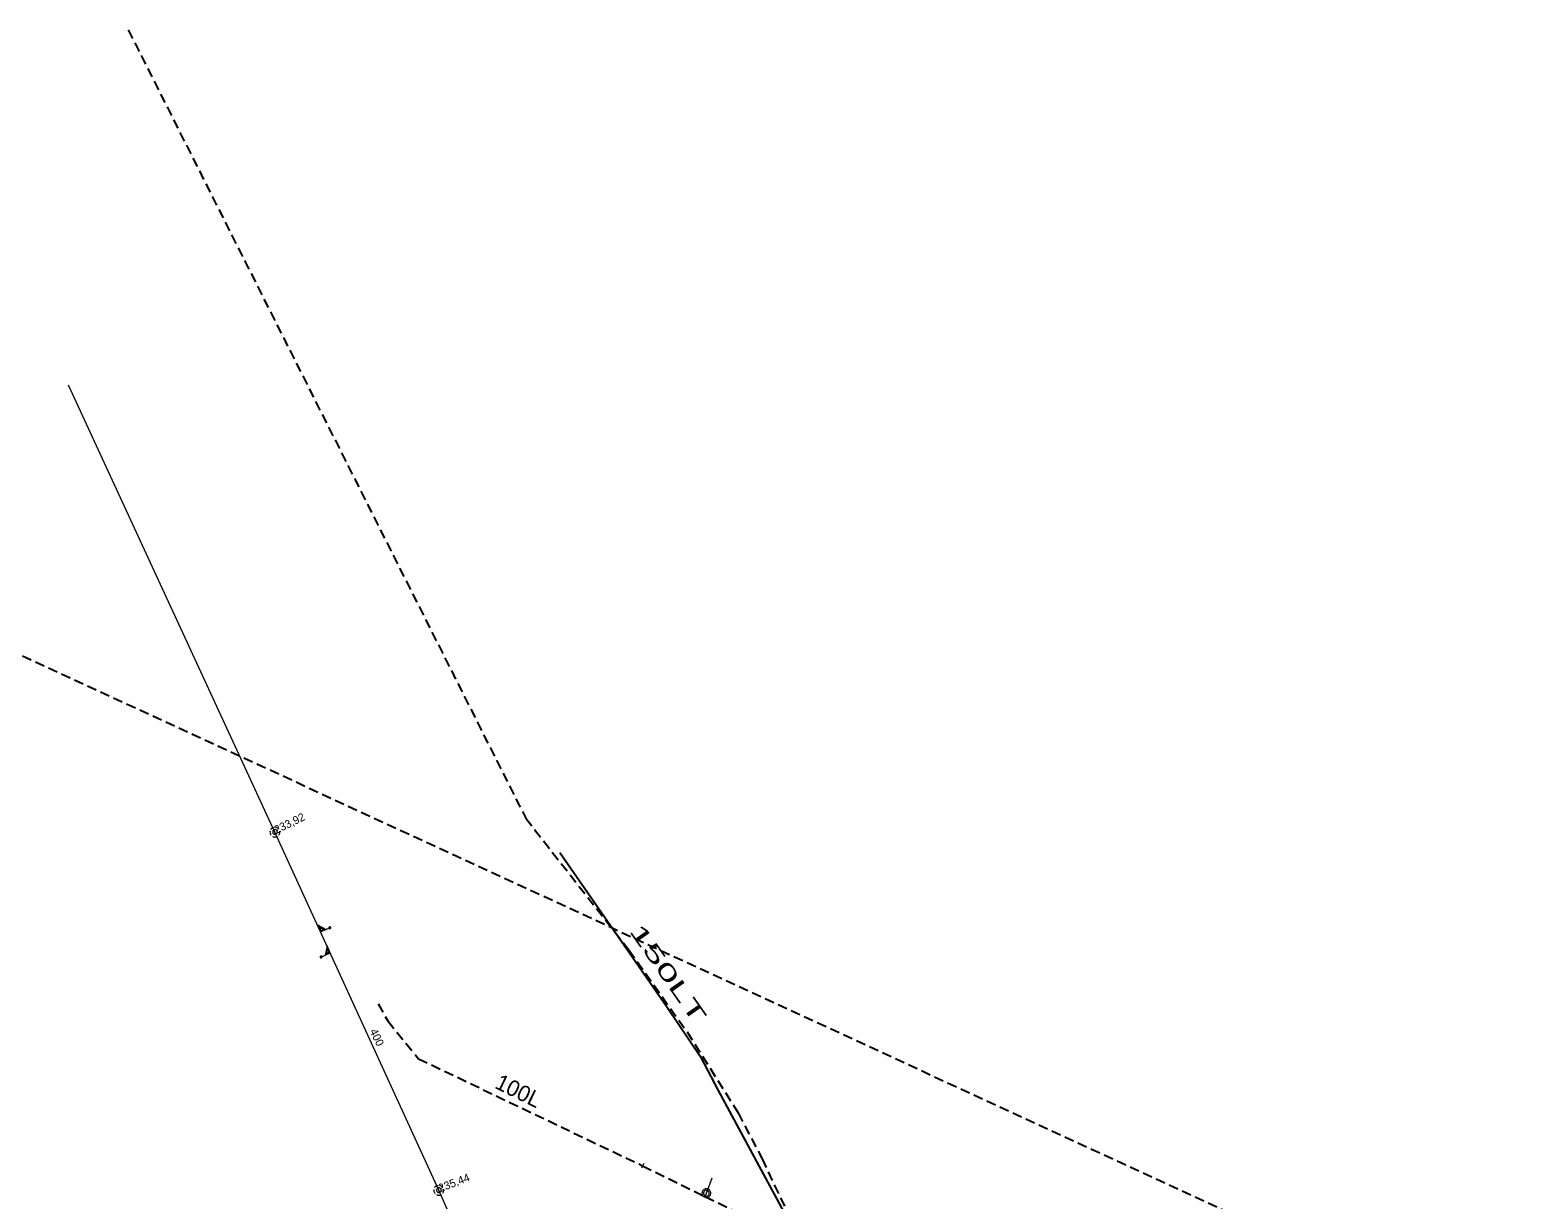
# Model space of a CAD drawing. Extents: x -735085 to -733500, y -1044153 to -1043402.
# Drawn here: x -734892.7 to -734742.3, y -1043519.6 to -1043402.3 of the extents above; entities that cross this region are included whole.
import ezdxf

# ---------------------------------------------------------------- set-up
doc = ezdxf.new("R2010")
doc.units = 0
doc.header["$LTSCALE"] = 0.32
doc.linetypes.add('MEDIUM_DASHED', pattern=[4.5, 3, -1.5])
doc.layers.add('15', color=7, linetype='Continuous')
doc.layers.add('16', color=7, linetype='Continuous')
for name, color, linetype, lineweight in [('18', 7, 'Continuous', 13), ('20', 7, 'Continuous', 13), ('63', 7, 'MEDIUM_DASHED', 25), ('8', 7, 'Continuous', 13)]:
    doc.layers.add(name, color=color, linetype=linetype, lineweight=lineweight)

msp = doc.modelspace()

# ---------------------------------------------------------------- linework, layer by layer
at = {"layer": '18'}
for points in [[(-734868.658, -1043482.699), (-734868.664, -1043482.776), (-734868.659, -1043482.853), (-734868.642, -1043482.928), (-734868.613, -1043482.999), (-734868.573, -1043483.065), (-734868.557, -1043483.087)], [(-734868.313, -1043482.307), (-734868.384, -1043482.335), (-734868.451, -1043482.374), (-734868.511, -1043482.422), (-734868.562, -1043482.479), (-734868.586, -1043482.513)], [(-734867.772, -1043482.49), (-734867.822, -1043482.432), (-734867.88, -1043482.382), (-734867.945, -1043482.341), (-734868.016, -1043482.312), (-734868.065, -1043482.298)], [(-734867.777, -1043483.076), (-734867.736, -1043483.011), (-734867.705, -1043482.941), (-734867.686, -1043482.866), (-734867.678, -1043482.79), (-734867.683, -1043482.713), (-734867.689, -1043482.678)], [(-734868.4, -1043483.216), (-734868.33, -1043483.247), (-734868.255, -1043483.266), (-734868.179, -1043483.273), (-734868.102, -1043483.268), (-734868.027, -1043483.251), (-734867.955, -1043483.223), (-734867.895, -1043483.188)], [(-734862.571, -1043492.344), (-734863.567, -1043492.8), (-734863.887, -1043492.099), (-734863.041, -1043492.559)], [(-734863.169, -1043492.563), (-734863.548, -1043492.736), (-734863.783, -1043492.221), (-734863.169, -1043492.562)], [(-734863.265, -1043492.555), (-734863.531, -1043492.676), (-734863.686, -1043492.338), (-734863.265, -1043492.556)], [(-734863.613, -1043495.348), (-734862.617, -1043494.892), (-734862.938, -1043494.191), (-734863.143, -1043495.133)], [(-734863.056, -1043495.037), (-734862.678, -1043494.864), (-734862.913, -1043494.349), (-734863.058, -1043495.038)], [(-734863, -1043494.959), (-734862.734, -1043494.838), (-734862.889, -1043494.501), (-734863, -1043494.96)], [(-734852.217, -1043518.649), (-734852.223, -1043518.726), (-734852.218, -1043518.803), (-734852.201, -1043518.878), (-734852.172, -1043518.949), (-734852.132, -1043519.015), (-734852.116, -1043519.037)], [(-734851.872, -1043518.257), (-734851.943, -1043518.285), (-734852.01, -1043518.324), (-734852.07, -1043518.372), (-734852.121, -1043518.429), (-734852.145, -1043518.463)], [(-734851.959, -1043519.166), (-734851.889, -1043519.197), (-734851.814, -1043519.216), (-734851.738, -1043519.223), (-734851.661, -1043519.218), (-734851.586, -1043519.201), (-734851.514, -1043519.173), (-734851.454, -1043519.138)], [(-734851.331, -1043518.44), (-734851.381, -1043518.382), (-734851.439, -1043518.332), (-734851.504, -1043518.291), (-734851.575, -1043518.262), (-734851.624, -1043518.248)], [(-734851.336, -1043519.026), (-734851.295, -1043518.961), (-734851.264, -1043518.891), (-734851.245, -1043518.816), (-734851.237, -1043518.74), (-734851.242, -1043518.663), (-734851.248, -1043518.628)]]:
    msp.add_lwpolyline(points, dxfattribs=at)
for points in [[(-734867.929, -1043482.759), (-734867.935, -1043482.707), (-734867.953, -1043482.657), (-734867.981, -1043482.613), (-734868.019, -1043482.576), (-734868.064, -1043482.549), (-734868.114, -1043482.533), (-734868.166, -1043482.528), (-734868.218, -1043482.535), (-734868.267, -1043482.554), (-734868.311, -1043482.584), (-734868.346, -1043482.623), (-734868.372, -1043482.668), (-734868.387, -1043482.719), (-734868.39, -1043482.771), (-734868.382, -1043482.823), (-734868.361, -1043482.871), (-734868.331, -1043482.914), (-734868.291, -1043482.949), (-734868.245, -1043482.973), (-734868.194, -1043482.987), (-734868.142, -1043482.989), (-734868.09, -1043482.979), (-734868.042, -1043482.957), (-734868, -1043482.925), (-734867.967, -1043482.885), (-734867.943, -1043482.838), (-734867.931, -1043482.787)], [(-734862.696, -1043492.298), (-734862.723, -1043492.317), (-734862.743, -1043492.344), (-734862.751, -1043492.377), (-734862.747, -1043492.41), (-734862.732, -1043492.44), (-734862.707, -1043492.462), (-734862.676, -1043492.476), (-734862.642, -1043492.477), (-734862.611, -1043492.466), (-734862.585, -1043492.445), (-734862.568, -1043492.416), (-734862.562, -1043492.383), (-734862.568, -1043492.351), (-734862.585, -1043492.321), (-734862.611, -1043492.3), (-734862.643, -1043492.29), (-734862.677, -1043492.291)], [(-734862.685, -1043492.323), (-734862.708, -1043492.34), (-734862.723, -1043492.364), (-734862.724, -1043492.392), (-734862.715, -1043492.419), (-734862.696, -1043492.44), (-734862.669, -1043492.449), (-734862.641, -1043492.449), (-734862.616, -1043492.436), (-734862.598, -1043492.415), (-734862.591, -1043492.387), (-734862.595, -1043492.359), (-734862.61, -1043492.336), (-734862.635, -1043492.32), (-734862.662, -1043492.316)], [(-734863.567, -1043495.222), (-734863.595, -1043495.241), (-734863.614, -1043495.269), (-734863.622, -1043495.301), (-734863.618, -1043495.334), (-734863.603, -1043495.364), (-734863.579, -1043495.387), (-734863.547, -1043495.4), (-734863.514, -1043495.401), (-734863.482, -1043495.391), (-734863.456, -1043495.369), (-734863.439, -1043495.341), (-734863.433, -1043495.308), (-734863.44, -1043495.275), (-734863.456, -1043495.246), (-734863.482, -1043495.225), (-734863.514, -1043495.215), (-734863.548, -1043495.216)], [(-734863.554, -1043495.246), (-734863.577, -1043495.263), (-734863.591, -1043495.288), (-734863.594, -1043495.316), (-734863.583, -1043495.343), (-734863.564, -1043495.363), (-734863.538, -1043495.374), (-734863.51, -1043495.373), (-734863.484, -1043495.36), (-734863.467, -1043495.338), (-734863.459, -1043495.311), (-734863.464, -1043495.283), (-734863.478, -1043495.26), (-734863.503, -1043495.244), (-734863.531, -1043495.24)], [(-734851.488, -1043518.709), (-734851.494, -1043518.657), (-734851.512, -1043518.607), (-734851.54, -1043518.563), (-734851.578, -1043518.526), (-734851.623, -1043518.499), (-734851.673, -1043518.483), (-734851.725, -1043518.478), (-734851.777, -1043518.485), (-734851.826, -1043518.504), (-734851.87, -1043518.534), (-734851.905, -1043518.573), (-734851.931, -1043518.618), (-734851.946, -1043518.669), (-734851.949, -1043518.721), (-734851.941, -1043518.773), (-734851.92, -1043518.821), (-734851.89, -1043518.864), (-734851.85, -1043518.899), (-734851.804, -1043518.923), (-734851.753, -1043518.937), (-734851.701, -1043518.939), (-734851.649, -1043518.929), (-734851.601, -1043518.907), (-734851.559, -1043518.875), (-734851.526, -1043518.835), (-734851.502, -1043518.788), (-734851.49, -1043518.737)]]:
    msp.add_lwpolyline(points, close=True, dxfattribs=at)
at = {"layer": '20'}
msp.add_line((-734827.03, -1043574.42), (-734851.719, -1043518.72), dxfattribs=at)
msp.add_line((-734827.03, -1043574.42), (-734851.719, -1043518.72), dxfattribs=at)
msp.add_lwpolyline([(-734851.719, -1043518.72), (-734868.16, -1043482.77), (-734888.879, -1043437.93)], dxfattribs=at)
msp.add_lwpolyline([(-734851.719, -1043518.72), (-734868.16, -1043482.77), (-734888.879, -1043437.93)], dxfattribs=at)
at = {"layer": '63'}
msp.add_lwpolyline([(-734796.022, -1043808.279), (-734957.658, -1043641.023), (-734957.66, -1043641.021), (-735032.487, -1043496.398), (-735032.488, -1043496.396), (-735032.488, -1043496.394), (-735032.488, -1043496.393), (-735032.488, -1043496.391), (-735014.686, -1043433.916), (-735014.686, -1043433.914), (-735014.685, -1043433.913), (-735014.683, -1043433.911), (-735014.682, -1043433.91), (-735014.68, -1043433.909), (-735014.678, -1043433.909), (-735014.676, -1043433.909), (-734957.569, -1043435.5), (-734957.567, -1043435.5), (-734957.565, -1043435.501), (-734250.468, -1043761.931)], dxfattribs=at)
at = {"layer": '8'}
msp.add_line((-734831.162, -1043516.042), (-734831.385, -1043516.509), dxfattribs=at)
at = {"layer": '8', "linetype": 'MEDIUM_DASHED', "lineweight": 25}
for points in [[(-734882.879, -1043402.28), (-734843, -1043481.39), (-734832.66, -1043494.6), (-734826.809, -1043502.83), (-734821.69, -1043510.97), (-734819.3, -1043515.56), (-734816.109, -1043522.33)], [(-734857.796, -1043500.009), (-734856.844, -1043501.735), (-734853.754, -1043505.523), (-734831.274, -1043516.278)], [(-734831.274, -1043516.278), (-734824.991, -1043519.356), (-734816.498, -1043523.517), (-734816.333, -1043523.597)]]:
    msp.add_lwpolyline(points, dxfattribs=at)
at = {"layer": '8', "lineweight": 25}
msp.add_lwpolyline([(-734839.59, -1043484.83), (-734833.43, -1043493.7), (-734828.809, -1043500.35), (-734825.489, -1043505.26), (-734823.69, -1043508.71), (-734816.69, -1043521.74), (-734815.949, -1043522.67)], dxfattribs=at)
at = {"layer": '8'}
msp.add_lwpolyline([(-734824.991, -1043519.356), (-734824.868, -1043519.024), (-734824.293, -1043517.48)], dxfattribs=at)
for points in [[(-734824.721, -1043518.6), (-734824.792, -1043518.58), (-734824.865, -1043518.572), (-734824.937, -1043518.576), (-734825.009, -1043518.592), (-734825.077, -1043518.619), (-734825.139, -1043518.657), (-734825.194, -1043518.704), (-734825.242, -1043518.76), (-734825.279, -1043518.823), (-734825.306, -1043518.892), (-734825.321, -1043518.963), (-734825.324, -1043519.037), (-734825.315, -1043519.109), (-734825.295, -1043519.179), (-734825.263, -1043519.245), (-734825.221, -1043519.305), (-734825.169, -1043519.357), (-734825.11, -1043519.4), (-734825.045, -1043519.433), (-734824.975, -1043519.455), (-734824.903, -1043519.465), (-734824.83, -1043519.463), (-734824.757, -1043519.45), (-734824.689, -1043519.424), (-734824.625, -1043519.388), (-734824.569, -1043519.342), (-734824.52, -1043519.288), (-734824.481, -1043519.225), (-734824.452, -1043519.158), (-734824.435, -1043519.087), (-734824.43, -1043519.014), (-734824.437, -1043518.941), (-734824.456, -1043518.87), (-734824.485, -1043518.803), (-734824.527, -1043518.742), (-734824.576, -1043518.688), (-734824.634, -1043518.644), (-734824.698, -1043518.61)], [(-734824.777, -1043518.751), (-734824.834, -1043518.736), (-734824.893, -1043518.734), (-734824.95, -1043518.742), (-734825.005, -1043518.763), (-734825.055, -1043518.794), (-734825.097, -1043518.835), (-734825.13, -1043518.883), (-734825.152, -1043518.938), (-734825.163, -1043518.995), (-734825.161, -1043519.054), (-734825.149, -1043519.111), (-734825.124, -1043519.164), (-734825.09, -1043519.211), (-734825.046, -1043519.251), (-734824.996, -1043519.28), (-734824.94, -1043519.299), (-734824.882, -1043519.305), (-734824.823, -1043519.3), (-734824.768, -1043519.283), (-734824.716, -1043519.255), (-734824.672, -1043519.217), (-734824.635, -1043519.171), (-734824.609, -1043519.119), (-734824.595, -1043519.062), (-734824.591, -1043519.004), (-734824.6, -1043518.946), (-734824.622, -1043518.891), (-734824.652, -1043518.842), (-734824.693, -1043518.8), (-734824.742, -1043518.767)]]:
    msp.add_lwpolyline(points, close=True, dxfattribs=at)

# ---------------------------------------------------------------- texts
at = {"layer": '15', "width": 1.9}
msp.add_text('150LT ', height=1.6, rotation=305, dxfattribs=at).set_placement((-734832.683, -1043492.698))
at = {"layer": '15'}
msp.add_text('100L', height=1.6, rotation=334, dxfattribs=at).set_placement((-734846.215, -1043508.423))
at = {"layer": '16'}
for s, rotation, p in [('233,92', 26, (-734868.014, -1043482.963)), ('400 ', 296, (-734858.685, -1043502.751)), ('235,44', 21, (-734851.591, -1043518.924))]:
    msp.add_text(s, height=0.8, rotation=rotation, dxfattribs=at).set_placement(p)

doc.saveas('drawing.dxf')
